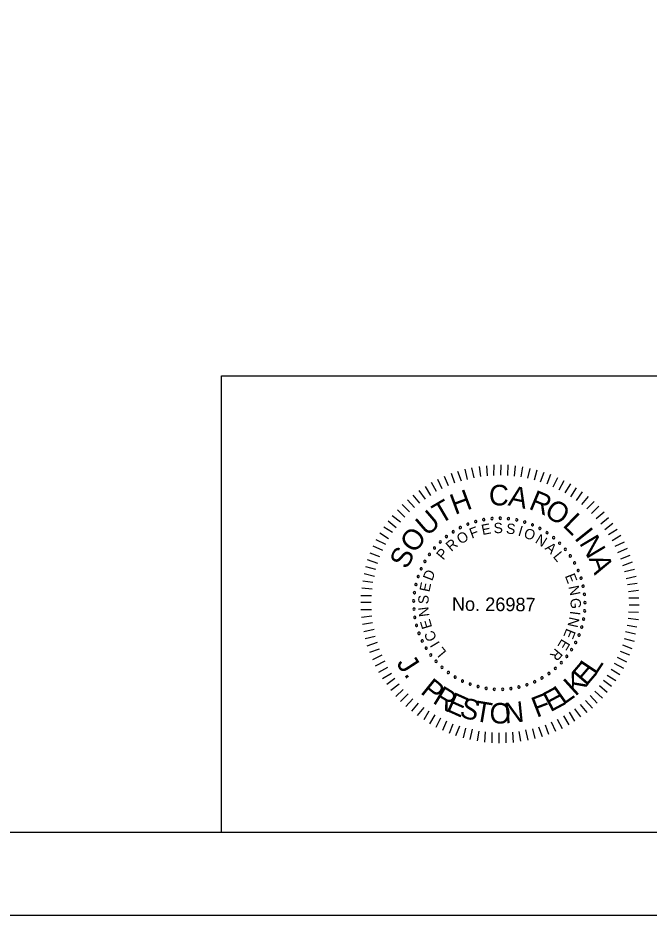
# Model space of a CAD drawing. Extents: x 1970675.2 to 1970711.3, y 796145.2 to 796167.2.
# Drawn here: x 1970696.64 to 1970700.45, y 796145.25 to 796150.65 of the extents above; entities that cross this region are included whole.
import ezdxf

# ---------------------------------------------------------------- set-up
doc = ezdxf.new("R2010")
doc.units = 0
for name, color, linetype in [('BR_BORDER LINES', 7, 'Continuous'), ('BR_TEXT', 7, 'Continuous'), ('Level 31', 7, 'Continuous')]:
    doc.layers.add(name, color=color, linetype=linetype)

msp = doc.modelspace()

# ---------------------------------------------------------------- linework, layer by layer
at = {"layer": 'BR_BORDER LINES'}
for p, q in [((1970697.8703, 796148.4964), (1970703.2355, 796148.4964)), ((1970697.8703, 796145.7463), (1970697.8703, 796148.4964)), ((1970677.0698, 796145.7463), (1970710.7358, 796145.7463))]:
    msp.add_line(p, q, dxfattribs=at)
at = {"layer": 'BR_TEXT'}
for p, q in [((1970699.511, 796147.8957), (1970699.5116, 796147.96)), ((1970699.5531, 796147.8979), (1970699.5536, 796147.9597)), ((1970699.5951, 796147.895), (1970699.5974, 796147.9593)), ((1970699.2755, 796147.8495), (1970699.2545, 796147.9081)), ((1970699.3151, 796147.8621), (1970699.2932, 796147.9198)), ((1970699.3512, 796147.8721), (1970699.338, 796147.9331)), ((1970699.3925, 796147.882), (1970699.3784, 796147.9414)), ((1970699.432, 796147.8895), (1970699.4231, 796147.9504)), ((1970699.4715, 796147.8934), (1970699.4677, 796147.9544)), ((1970699.6354, 796147.8921), (1970699.6402, 796147.9529)), ((1970699.674, 796147.8875), (1970699.6848, 796147.9483)), ((1970699.7143, 796147.8794), (1970699.7285, 796147.9385)), ((1970699.7554, 796147.8688), (1970699.7713, 796147.9295)), ((1970699.7922, 796147.8582), (1970699.8141, 796147.9155)), ((1970699.8316, 796147.8449), (1970699.8535, 796147.9031)), ((1970699.1652, 796147.7981), (1970699.1348, 796147.8524)), ((1970699.1997, 796147.8158), (1970699.1735, 796147.8718)), ((1970699.2368, 796147.8327), (1970699.2132, 796147.8887)), ((1970699.8675, 796147.8275), (1970699.8954, 796147.883)), ((1970699.9034, 796147.81), (1970699.9347, 796147.8656)), ((1970699.0988, 796147.7532), (1970699.0597, 796147.8041)), ((1970699.1299, 796147.7744), (1970699.0994, 796147.8287)), ((1970699.941, 796147.7917), (1970699.9732, 796147.8455)), ((1970699.9743, 796147.7674), (1970700.0082, 796147.8212)), ((1970700.0075, 796147.7457), (1970700.044, 796147.796)), ((1970699.0323, 796147.7031), (1970698.9906, 796147.748)), ((1970699.0651, 796147.7277), (1970699.0252, 796147.7778)), ((1970700.0399, 796147.7197), (1970700.0806, 796147.7691)), ((1970700.0715, 796147.6945), (1970700.1147, 796147.7388)), ((1970698.9735, 796147.6452), (1970698.93, 796147.6876)), ((1970699.0029, 796147.6759), (1970698.9586, 796147.72)), ((1970700.0995, 796147.6668), (1970700.1428, 796147.7102)), ((1970698.9483, 796147.6137), (1970698.8988, 796147.6527)), ((1970700.1276, 796147.6357), (1970700.1752, 796147.6774)), ((1970700.1548, 796147.6037), (1970700.2015, 796147.6419)), ((1970698.9006, 796147.5514), (1970698.8468, 796147.5845)), ((1970698.9223, 796147.5804), (1970698.8728, 796147.6203)), ((1970700.1786, 796147.57), (1970700.2278, 796147.6091)), ((1970698.8762, 796147.5147), (1970698.8225, 796147.5469)), ((1970700.2006, 796147.5407), (1970700.2532, 796147.5729)), ((1970700.2226, 796147.5036), (1970700.2761, 796147.5349)), ((1970698.8413, 796147.4438), (1970698.7841, 796147.4692)), ((1970698.8588, 796147.4805), (1970698.8024, 796147.5085)), ((1970700.2404, 796147.4691), (1970700.2981, 796147.4961)), ((1970698.8238, 796147.4053), (1970698.7657, 796147.4272)), ((1970700.2581, 796147.4321), (1970700.315, 796147.4565)), ((1970700.2749, 796147.3933), (1970700.3318, 796147.4143)), ((1970698.8115, 796147.3651), (1970698.7499, 796147.3879)), ((1970700.2883, 796147.3529), (1970700.346, 796147.3747)), ((1970698.7992, 796147.3291), (1970698.7384, 796147.3442)), ((1970700.2984, 796147.3168), (1970700.3585, 796147.3308)), ((1970698.7814, 796147.2512), (1970698.7205, 796147.2594)), ((1970698.792, 796147.2871), (1970698.7295, 796147.3031)), ((1970700.3066, 796147.2746), (1970700.3668, 796147.2896)), ((1970698.7768, 796147.21), (1970698.715, 796147.2174)), ((1970700.3149, 796147.2385), (1970700.3741, 796147.2458)), ((1970700.3214, 796147.1973), (1970700.3824, 796147.2036)), ((1970698.7738, 796147.1706), (1970698.7095, 796147.1711)), ((1970700.3228, 796147.1578), (1970700.3829, 796147.1573)), ((1970698.7718, 796147.1294), (1970698.7092, 796147.1299)), ((1970700.325, 796147.1166), (1970700.3859, 796147.1161)), ((1970698.7732, 796147.0865), (1970698.7088, 796147.0853)), ((1970698.7754, 796147.0478), (1970698.7136, 796147.0406)), ((1970700.3221, 796147.0737), (1970700.3822, 796147.0715)), ((1970698.7794, 796147.0066), (1970698.7183, 796146.9977)), ((1970700.3129, 796146.994), (1970700.372, 796146.984)), ((1970700.32, 796147.0351), (1970700.3809, 796147.0269)), ((1970698.7893, 796146.9671), (1970698.7266, 796146.9539)), ((1970700.3039, 796146.9546), (1970700.3639, 796146.9403)), ((1970698.7959, 796146.9249), (1970698.7348, 796146.9109)), ((1970698.8076, 796146.888), (1970698.7456, 796146.867)), ((1970700.2844, 796146.8758), (1970700.3417, 796146.8538)), ((1970700.295, 796146.9126), (1970700.3549, 796146.8975)), ((1970698.8192, 796146.8493), (1970698.7607, 796146.8283)), ((1970700.2704, 796146.8373), (1970700.3268, 796146.8153)), ((1970698.8361, 796146.8122), (1970698.7784, 796146.7852)), ((1970698.853, 796146.776), (1970698.7961, 796146.7465)), ((1970700.2529, 796146.8005), (1970700.3093, 796146.7726)), ((1970698.8698, 796146.739), (1970698.8155, 796146.7077)), ((1970700.2162, 796146.7279), (1970700.2692, 796146.6957)), ((1970700.2346, 796146.7646), (1970700.2918, 796146.7341)), ((1970698.8936, 796146.7019), (1970698.8392, 796146.6706)), ((1970698.9148, 796146.6725), (1970698.8647, 796146.636)), ((1970700.1711, 796146.6622), (1970700.2197, 796146.6248)), ((1970700.1936, 796146.6911), (1970700.2457, 796146.659)), ((1970698.9402, 796146.6388), (1970698.8901, 796146.5998)), ((1970698.9649, 796146.6052), (1970698.9207, 796146.5643)), ((1970700.1468, 796146.6289), (1970700.1928, 796146.589)), ((1970698.9938, 796146.5792), (1970698.9488, 796146.5341)), ((1970699.0227, 796146.5489), (1970698.9803, 796146.5029)), ((1970700.0905, 796146.5701), (1970700.133, 796146.5243)), ((1970700.119, 796146.5956), (1970700.1659, 796146.5541)), ((1970699.0552, 796146.5229), (1970699.0144, 796146.476)), ((1970699.0884, 796146.4969), (1970699.0485, 796146.4492)), ((1970700.03, 796146.5149), (1970700.0699, 796146.4673)), ((1970700.0619, 796146.5403), (1970700.1044, 796146.4936)), ((1970699.1191, 796146.4752), (1970699.0878, 796146.4231)), ((1970699.1541, 796146.4526), (1970699.1228, 796146.3988)), ((1970699.9299, 796146.4462), (1970699.9612, 796146.3918)), ((1970699.9635, 796146.4682), (1970699.9966, 796146.4156)), ((1970699.9972, 796146.4894), (1970700.0328, 796146.441)), ((1970699.1883, 796146.4326), (1970699.1612, 796146.377)), ((1970699.225, 796146.4151), (1970699.2005, 796146.3595)), ((1970699.2635, 796146.3976), (1970699.2416, 796146.3411)), ((1970699.8196, 796146.393), (1970699.8406, 796146.3362)), ((1970699.8558, 796146.4099), (1970699.8827, 796146.3539)), ((1970699.8919, 796146.4267), (1970699.9224, 796146.3707)), ((1970699.3029, 796146.3853), (1970699.2801, 796146.3271)), ((1970699.3388, 796146.3729), (1970699.3246, 796146.3139)), ((1970699.38, 796146.3658), (1970699.3648, 796146.3041)), ((1970699.4193, 796146.3543), (1970699.4094, 796146.296)), ((1970699.4588, 796146.3497), (1970699.454, 796146.2879)), ((1970699.4982, 796146.3468), (1970699.4977, 796146.285)), ((1970699.5402, 796146.3438), (1970699.5397, 796146.2829)), ((1970699.5823, 796146.3461), (1970699.5835, 796146.2842)), ((1970699.6227, 796146.3483), (1970699.6264, 796146.2865)), ((1970699.6613, 796146.3523), (1970699.6712, 796146.2938)), ((1970699.7018, 796146.3631), (1970699.715, 796146.3012)), ((1970699.743, 796146.3696), (1970699.758, 796146.3103)), ((1970699.78, 796146.3813), (1970699.801, 796146.3228))]:
    msp.add_line(p, q, dxfattribs=at)
for centre, start, end in [((1970699.4496, 796147.6294), 10.6038, 190.6038), ((1970699.4496, 796147.6294), 190.6038, 10.6038), ((1970699.499, 796147.6361), 5.0653, 185.0653), ((1970699.499, 796147.6361), 185.0653, 5.0653), ((1970699.5488, 796147.638), 359.5268, 179.5268), ((1970699.5488, 796147.638), 179.5268, 359.5268), ((1970699.5985, 796147.635), 173.9884, 353.9884), ((1970699.5985, 796147.635), 353.9884, 173.9884), ((1970699.6478, 796147.6273), 348.4499, 168.4499), ((1970699.3085, 796147.5813), 27.2191, 207.2191), ((1970699.3085, 796147.5813), 207.2191, 27.2191), ((1970699.3539, 796147.6019), 21.6807, 201.6807), ((1970699.3539, 796147.6019), 201.6807, 21.6807), ((1970699.4011, 796147.6179), 16.1422, 196.1422), ((1970699.4011, 796147.6179), 196.1422, 16.1422), ((1970699.6478, 796147.6273), 168.4499, 348.4499), ((1970699.696, 796147.6149), 162.9114, 342.9114), ((1970699.696, 796147.6149), 342.9114, 162.9114), ((1970699.7429, 796147.5979), 157.373, 337.373), ((1970699.7429, 796147.5979), 337.373, 157.373), ((1970699.7878, 796147.5764), 151.8345, 331.8345), ((1970699.7878, 796147.5764), 331.8345, 151.8345), ((1970699.2247, 796147.5276), 38.2961, 218.2961), ((1970699.2247, 796147.5276), 218.2961, 38.2961), ((1970699.2653, 796147.5565), 32.7576, 212.7576), ((1970699.2653, 796147.5565), 212.7576, 32.7576), ((1970699.8305, 796147.5507), 146.2961, 326.2961), ((1970699.8305, 796147.5507), 326.2961, 146.2961), ((1970699.8705, 796147.521), 140.7576, 320.7576), ((1970699.8705, 796147.521), 320.7576, 140.7576), ((1970699.1871, 796147.495), 43.8345, 223.8345), ((1970699.1871, 796147.495), 223.8345, 43.8345), ((1970699.9075, 796147.4876), 135.2191, 315.2191), ((1970699.9075, 796147.4876), 315.2191, 135.2191), ((1970699.1221, 796147.4196), 54.9114, 234.9114), ((1970699.1221, 796147.4196), 234.9114, 54.9114), ((1970699.1528, 796147.4588), 49.373, 229.373), ((1970699.1528, 796147.4588), 229.373, 49.373), ((1970699.9411, 796147.4508), 129.6807, 309.6807), ((1970699.9411, 796147.4508), 309.6807, 129.6807), ((1970699.9709, 796147.4109), 124.1422, 304.1422), ((1970699.9709, 796147.4109), 304.1422, 124.1422), ((1970699.0954, 796147.3775), 60.4499, 240.4499), ((1970699.0954, 796147.3775), 240.4499, 60.4499), ((1970699.9968, 796147.3683), 118.6038, 298.6038), ((1970699.9968, 796147.3683), 298.6038, 118.6038), ((1970699.0729, 796147.3331), 65.9884, 245.9884), ((1970699.0729, 796147.3331), 245.9884, 65.9884), ((1970700.0184, 796147.3234), 113.0653, 293.0653), ((1970700.0184, 796147.3234), 293.0653, 113.0653), ((1970699.0547, 796147.2867), 71.5268, 251.5268), ((1970699.0547, 796147.2867), 251.5268, 71.5268), ((1970700.0356, 796147.2766), 107.5268, 287.5268), ((1970700.0356, 796147.2766), 287.5268, 107.5268), ((1970699.0411, 796147.2387), 77.0653, 257.0653), ((1970699.0411, 796147.2387), 257.0653, 77.0653), ((1970700.0482, 796147.2284), 101.9884, 281.9884), ((1970700.0482, 796147.2284), 281.9884, 101.9884), ((1970699.0281, 796147.14), 88.1422, 268.1422), ((1970699.0322, 796147.1897), 82.6038, 262.6038), ((1970699.0281, 796147.14), 268.1422, 88.1422), ((1970699.0322, 796147.1897), 262.6038, 82.6038), ((1970700.0561, 796147.1792), 96.4499, 276.4499), ((1970700.0561, 796147.1792), 276.4499, 96.4499), ((1970699.0288, 796147.0902), 93.6807, 273.6807), ((1970699.0288, 796147.0902), 273.6807, 93.6807), ((1970700.0592, 796147.1295), 90.9114, 270.9114), ((1970700.0592, 796147.1295), 270.9114, 90.9114), ((1970699.0343, 796147.0407), 99.2191, 279.2191), ((1970699.0343, 796147.0407), 279.2191, 99.2191), ((1970700.0509, 796147.0303), 79.8345, 259.8345), ((1970700.0509, 796147.0303), 259.8345, 79.8345), ((1970700.0575, 796147.0797), 85.373, 265.373), ((1970700.0575, 796147.0797), 265.373, 85.373), ((1970699.0446, 796146.9919), 104.7576, 284.7576), ((1970699.0446, 796146.9919), 284.7576, 104.7576), ((1970700.0397, 796146.9817), 74.2961, 254.2961), ((1970700.0397, 796146.9817), 254.2961, 74.2961), ((1970699.0595, 796146.9444), 110.2961, 290.2961), ((1970699.0595, 796146.9444), 290.2961, 110.2961), ((1970700.0238, 796146.9345), 68.7576, 248.7576), ((1970700.0238, 796146.9345), 248.7576, 68.7576), ((1970699.0789, 796146.8985), 115.8345, 295.8345), ((1970699.0789, 796146.8985), 295.8345, 115.8345), ((1970700.0034, 796146.889), 63.2191, 243.2191), ((1970700.0034, 796146.889), 243.2191, 63.2191), ((1970699.1027, 796146.8547), 121.373, 301.373), ((1970699.1027, 796146.8547), 301.373, 121.373), ((1970699.1306, 796146.8134), 306.9114, 126.9114), ((1970699.9788, 796146.8457), 57.6807, 237.6807), ((1970699.9788, 796146.8457), 237.6807, 57.6807), ((1970699.1306, 796146.8134), 126.9114, 306.9114), ((1970699.1623, 796146.775), 132.4499, 312.4499), ((1970699.1623, 796146.775), 312.4499, 132.4499), ((1970699.9175, 796146.7672), 46.6038, 226.6038), ((1970699.9175, 796146.7672), 226.6038, 46.6038), ((1970699.9501, 796146.805), 52.1422, 232.1422), ((1970699.9501, 796146.805), 232.1422, 52.1422), ((1970699.1976, 796146.7398), 137.9884, 317.9884), ((1970699.1976, 796146.7398), 317.9884, 137.9884), ((1970699.2361, 796146.7082), 143.5268, 323.5268), ((1970699.2361, 796146.7082), 323.5268, 143.5268), ((1970699.8815, 796146.7328), 41.0653, 221.0653), ((1970699.8815, 796146.7328), 221.0653, 41.0653), ((1970699.2775, 796146.6805), 149.0653, 329.0653), ((1970699.2775, 796146.6805), 329.0653, 149.0653), ((1970699.3214, 796146.6569), 154.6038, 334.6038), ((1970699.3214, 796146.6569), 334.6038, 154.6038), ((1970699.756, 796146.6524), 24.4499, 204.4499), ((1970699.8004, 796146.6751), 29.9884, 209.9884), ((1970699.8004, 796146.6751), 209.9884, 29.9884), ((1970699.8423, 796146.702), 35.5268, 215.5268), ((1970699.8423, 796146.702), 215.5268, 35.5268), ((1970699.3674, 796146.6376), 160.1422, 340.1422), ((1970699.3674, 796146.6376), 340.1422, 160.1422), ((1970699.415, 796146.6229), 165.6807, 345.6807), ((1970699.415, 796146.6229), 345.6807, 165.6807), ((1970699.4638, 796146.6128), 351.2191, 171.2191), ((1970699.4638, 796146.6128), 171.2191, 351.2191), ((1970699.5133, 796146.6075), 356.7576, 176.7576), ((1970699.5133, 796146.6075), 176.7576, 356.7576), ((1970699.5632, 796146.607), 2.2961, 182.2961), ((1970699.5632, 796146.607), 182.2961, 2.2961), ((1970699.6128, 796146.6113), 7.8345, 187.8345), ((1970699.6128, 796146.6113), 187.8345, 7.8345), ((1970699.6618, 796146.6203), 13.373, 193.373), ((1970699.6618, 796146.6203), 193.373, 13.373), ((1970699.7097, 796146.6341), 18.9114, 198.9114), ((1970699.7097, 796146.6341), 198.9114, 18.9114), ((1970699.756, 796146.6524), 204.4499, 24.4499)]:
    msp.add_arc(centre, 0.00701, start, end, dxfattribs=at)
at = {"layer": 'Level 31'}
msp.add_lwpolyline([(1970675.2365, 796145.2464), (1970711.2364, 796145.2464), (1970711.2364, 796167.2463), (1970675.2365, 796167.2463)], close=True, dxfattribs=at)

# ---------------------------------------------------------------- texts
at = {"layer": 'BR_TEXT'}
for s, height, rotation, p in [('H', 0.1241, 20.3637, (1970699.2759, 796147.6572)), ('C', 0.1241, 359.5482, (1970699.4803, 796147.7155)), ('A', 0.1241, 348.1981, (1970699.5917, 796147.7163)), ('R', 0.1241, 337.4344, (1970699.715, 796147.6965)), ('T', 0.1241, 30.4992, (1970699.188, 796147.5997)), ('O', 0.1239, 326.5869, (1970699.8072, 796147.6597)), ('U', 0.1241, 40.8022, (1970699.1068, 796147.525)), ('L', 0.1241, 315.9488, (1970699.9198, 796147.5919)), ('F', 0.0622, 20.6127, (1970699.3772, 796147.5143)), ('E', 0.0622, 11.4103, (1970699.4423, 796147.536)), ('S', 0.0622, 2.208, (1970699.5102, 796147.547)), ('S', 0.0622, 352.6608, (1970699.5814, 796147.5468)), ('I', 0.0622, 343.1136, (1970699.6517, 796147.5348)), ('O', 0.0622, 338.4392, (1970699.6851, 796147.5247)), ('I', 0.1241, 308.6613, (1970699.9912, 796147.5176)), ('O', 0.1241, 52.0267, (1970699.0323, 796147.421)), ('O', 0.0622, 30.8477, (1970699.3098, 796147.4783)), ('N', 0.0622, 328.2042, (1970699.7547, 796147.4933)), ('N', 0.1241, 300.7037, (1970700.0218, 796147.4883)), ('R', 0.0622, 40.3949, (1970699.2537, 796147.4344)), ('A', 0.0622, 318.657, (1970699.8137, 796147.4532)), ('S', 0.1239, 63.2511, (1970698.9869, 796147.3254)), ('P', 0.0622, 49.9421, (1970699.2056, 796147.3818)), ('L', 0.0622, 309.4546, (1970699.8635, 796147.4059)), ('A', 0.1241, 289.4792, (1970700.081, 796147.3952)), ('D', 0.0622, 69.0364, (1970699.1386, 796147.2566)), ('E', 0.0622, 291.049, (1970699.9373, 796147.2906)), ('E', 0.0622, 78.2388, (1970699.122, 796147.1899)), ('N', 0.0622, 281.8466, (1970699.9595, 796147.2256)), ('S', 0.0622, 87.786, (1970699.1163, 796147.1189)), ('No. 26987', 0.08175, 359.5268, (1970699.2574, 796147.0804)), ('G', 0.0622, 272.2995, (1970699.9713, 796147.1553)), ('N', 0.0622, 97.3332, (1970699.1225, 796147.0479)), ('N', 0.0622, 257.7339, (1970699.9664, 796147.0468)), ('I', 0.0622, 262.4084, (1970699.9709, 796147.0814)), ('E', 0.0622, 106.5355, (1970699.1395, 796146.9813)), ('C', 0.0622, 116.4266, (1970699.1694, 796146.9138)), ('E', 0.0622, 248.1867, (1970699.9483, 796146.9779)), ('I', 0.0622, 121.1011, (1970699.1875, 796146.8839)), ('E', 0.0622, 238.9844, (1970699.9204, 796146.9151)), ('L', 0.0622, 129.9595, (1970699.2281, 796146.8318)), ('R', 0.0622, 229.782, (1970699.8827, 796146.8577)), ('J', 0.1236, 302.9559, (1970698.9202, 796146.7633)), ('E', 0.1236, 49.3639, (1970700.0662, 796146.6214)), ('L', 0.1236, 56.4247, (1970700.1237, 796146.6891)), ('K', 0.1236, 42.3031, (1970700.0009, 796146.5613)), ('.', 0.1236, 309.3974, (1970698.9643, 796146.6953)), ('P', 0.1236, 321.1035, (1970699.0627, 796146.5861)), ('R', 0.1236, 328.5359, (1970699.136, 796146.528)), ('E', 0.1236, 28.1814, (1970699.8506, 796146.4673)), ('L', 0.1236, 35.2422, (1970699.9286, 796146.5097)), ('E', 0.1236, 335.9684, (1970699.2161, 796146.4799)), ('S', 0.1236, 343.0292, (1970699.2974, 796146.4442)), ('F', 0.1236, 21.1206, (1970699.7679, 796146.4348)), ('T', 0.1236, 350.4617, (1970699.3871, 796146.4177)), ('O', 0.1236, 358.1419, (1970699.4825, 796146.4028)), ('N', 0.1236, 5.8221, (1970699.579, 796146.4007))]:
    msp.add_text(s, height=height, rotation=rotation, dxfattribs=at).set_placement(p)

doc.saveas('drawing.dxf')
